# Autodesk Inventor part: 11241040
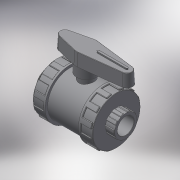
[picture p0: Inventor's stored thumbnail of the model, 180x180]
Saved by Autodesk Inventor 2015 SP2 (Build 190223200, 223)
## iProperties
Created: 2017-11
Part Number: 11241040
Material: Generic
Description: PLASSON BI STOP VALVE THR PVC 4"
Document SubType Name: Modeling
Designer: KIM
Density: 1 g/cm^3
Appearance: Default
Author: KIM
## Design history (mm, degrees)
derived "112410 - 112710.ipt"
feature "Solid1::112410 - 112710.ipt"
tag "TaggingFeature1"
body "Solid1"
other parameters: "d0" = 295, "d1" = 110.072, "d2" = 207, "d3" = 61, "d4" = 88.0576, "d5" = 42.7, "d7" = 154.1008, "d8" = 186.3, "d13" = 3.30216, "d23" = 61, "d24" = 198.72, "d25" = 2.20144, "d26" = 3.30216, "d27" = 31.05, "d28" = 15.525, "d29" = 45.75, "d30" = 0, "d35" = 3.30216, "d39" = 103.5, "d45" = 360 deg, "d47" = 2.20144, "d50" = 113.85, "d51" = 62.1, "d53" = 0, "d55" = 22.0144, "d56" = 11.0072, "d57" = 42.7, "d58" = 0, "d59" = 3.30216, "d61" = 360 deg, "d63" = 82.8, "d64" = 173, "d66" = 185, "d68" = 41.4, "d69" = 55.5, "d70" = 43.25, "d71" = 3 deg, "d73" = 4.14, "d74" = 74, "d75" = 5.19, "d76" = 0, "d77" = 2.20144, "G_" = 110.072, "l_" = 61, "H_" = 295, "K_" = 207, "F_" = 173, "J_" = 185, "d67" = 82.8, "d72" = 20.7
